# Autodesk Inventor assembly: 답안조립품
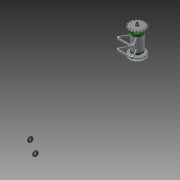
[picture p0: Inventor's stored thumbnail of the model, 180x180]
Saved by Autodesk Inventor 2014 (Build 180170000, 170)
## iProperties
Created: 2016-03
Part Number: 답안조립품
Document SubType Name: Assembly
Designer: 406-017
Author: 406-017
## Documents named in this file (15)
- C:\Users\406-017\Desktop\460307V1009\답안조립품.iam
- C:\Users\406-017\Desktop\460307V1009\부품1.ipt
- C:\Users\406-017\Desktop\460307V1009\축.ipt
- C:\Users\406-017\Desktop\460307V1009\와셔 8x17.ipt
- C:\Users\406-017\Desktop\460307V1009\키 3 x 3 x 12.ipt
- C:\Users\406-017\Desktop\460307V1009\스프링와셔 8.ipt
- C:\Users\406-017\Desktop\460307V1009\너트 M 8.ipt
- C:\Users\406-017\Desktop\460307V1009\V벨트풀리.ipt
- C:\Users\406-017\Desktop\460307V1009\스프로킷.ipt
- C:\Users\406-017\Desktop\460307V1009\니플 M 6 x 0.75.ipt
- C:\Users\406-017\Desktop\460307V1009\볼트 M 6 x 8.ipt
- C:\Users\406-017\Desktop\460307V1009\와셔 6x11.5.ipt
- C:\Users\406-017\Desktop\460307V1009\커버.ipt
- C:\Users\406-017\Desktop\460307V1009\베어링 15 x 32 x 9.ipt
- C:\Users\406-017\Desktop\460307V1009\오일 실 15 25 7.ipt
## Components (3 placed, 2 different names)
1. V벨트풀리:1 — 각도:3
2. KS B 2023 6002 - 15 x 32 x 9:1
3. KS B 2023 6002 - 15 x 32 x 9:2
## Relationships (1: Angle 1)
- 각도:3 [Angle]: V벨트풀리:1
